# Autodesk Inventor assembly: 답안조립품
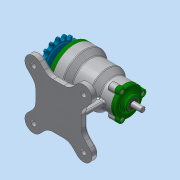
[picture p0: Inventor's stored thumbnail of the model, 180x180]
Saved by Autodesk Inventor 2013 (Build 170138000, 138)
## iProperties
Created: 2017-03
Part Number: 답안조립품
Document SubType Name: Assembly
Designer: Administrator
Author: Administrator
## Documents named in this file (14)
- C:\Users\Administrator\Desktop\470307V1004\답안조립품.iam
- C:\Users\Administrator\Desktop\470307V1004\본체.ipt
- C:\Users\Administrator\Desktop\470307V1004\뒤커버.ipt
- C:\Users\Administrator\Desktop\470307V1004\앞커버.ipt
- C:\Users\Administrator\Desktop\470307V1004\오일 실 10 20 7.ipt
- C:\Users\Administrator\Desktop\470307V1004\오일 실 17 30 8.ipt
- C:\Users\Administrator\Desktop\470307V1004\베어링-6200.ipt
- C:\Users\Administrator\Desktop\470307V1004\베어링-6203.ipt
- C:\Users\Administrator\Desktop\470307V1004\축.ipt
- C:\Users\Administrator\Desktop\470307V1004\키5x5.ipt
- C:\Users\Administrator\Desktop\470307V1004\스프로킷.ipt
- C:\Users\Administrator\Desktop\470307V1004\볼트 M4 x 12.ipt
- C:\Users\Administrator\Desktop\470307V1004\볼트 M5 x 10.ipt
- 볼트 M5 x 10.ipt
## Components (9 placed, 1 different names)
1. ISO 4762 M4 x 12:1
2. ISO 4762 M4 x 12:3
3. ISO 4762 M4 x 12:4
4. ISO 4762 M4 x 12:5
5. ISO 4762 M4 x 12:6
6. ISO 4762 M4 x 12:7
7. ISO 4762 M4 x 12:2
8. ISO 4762 M4 x 12:8
9. ISO 4762 M4 x 12:9
